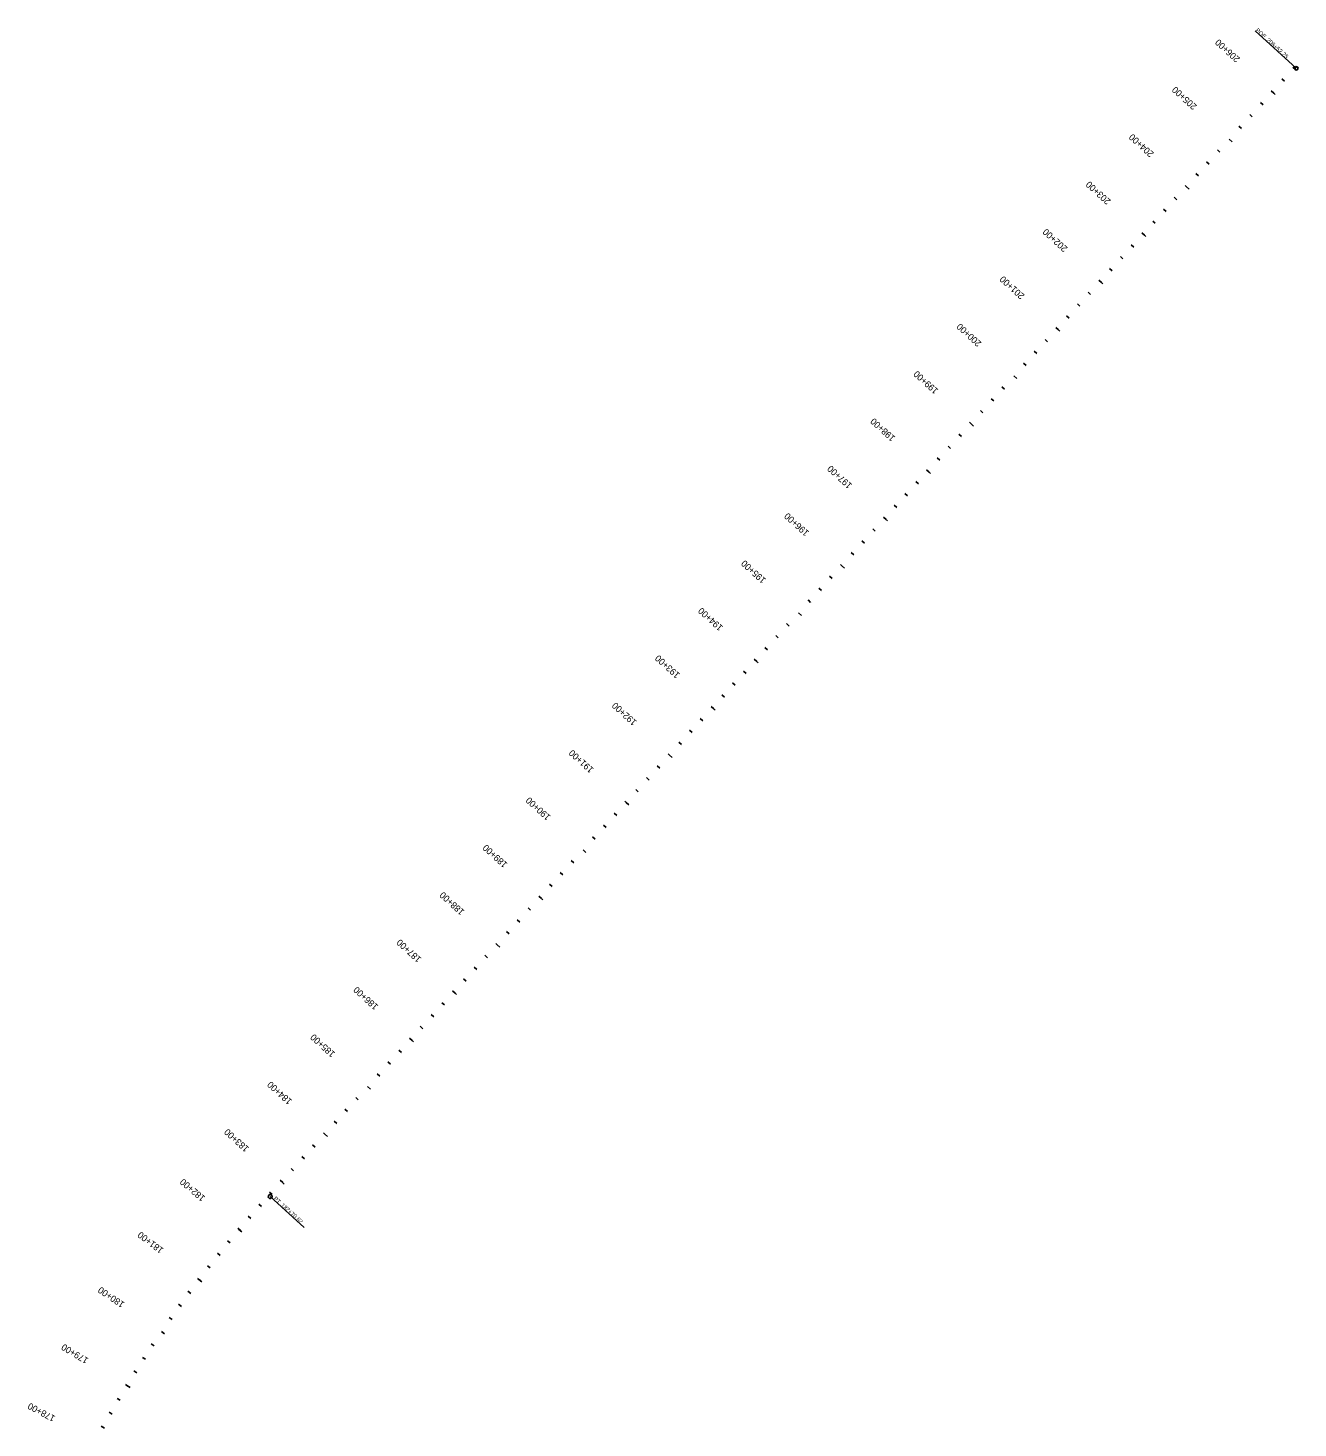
# Model space of a CAD drawing. Extents: x 17535628 to 17537899, y 7333852 to 7342653.
# Drawn here: x 17535915 to 17537899, y 7340467 to 7342653 of the extents above; entities that cross this region are included whole.
import ezdxf

# ---------------------------------------------------------------- set-up
doc = ezdxf.new("R2010")
doc.units = 0
for name, color, linetype in [('TextAlignment', 7, 'Continuous'), ('TextAlignmentLrg', 7, 'Continuous'), ('TextAlignmentSml', 7, 'Continuous')]:
    doc.layers.add(name, color=color, linetype=linetype)

msp = doc.modelspace()

# ---------------------------------------------------------------- linework, layer by layer
at = {"layer": 'TextAlignment'}
for p, q in [((17537895.9, 7342590.2), (17537831.6, 7342648.8)), ((17536293.2, 7340828.6), (17536346.4, 7340780.1))]:
    msp.add_line(p, q, dxfattribs=at)
for centre, radius in [((17537895.9, 7342590.2), 2.67), ((17536293.2, 7340828.6), 3.12)]:
    msp.add_circle(centre, radius, dxfattribs=at)
at = {"layer": 'TextAlignmentLrg'}
for p, q in [((17537860.7, 7342551.6), (17537856.7, 7342555.2)), ((17537791.2, 7342479.7), (17537795.7, 7342475.5)), ((17537726.1, 7342403.6), (17537722.1, 7342407.3)), ((17537658.9, 7342329.7), (17537654.8, 7342333.3)), ((17537591.6, 7342255.7), (17537587.5, 7342259.4)), ((17537524.3, 7342181.7), (17537520.2, 7342185.4)), ((17537454.7, 7342109.8), (17537459.2, 7342105.7)), ((17537389.7, 7342033.8), (17537385.6, 7342037.5)), ((17537322.4, 7341959.8), (17537318.3, 7341963.5)), ((17537255.1, 7341885.9), (17537251, 7341889.5)), ((17537187.8, 7341811.9), (17537183.7, 7341815.6)), ((17537118.2, 7341740), (17537122.8, 7341735.9)), ((17537053.2, 7341663.9), (17537049.2, 7341667.6)), ((17536985.9, 7341590), (17536981.9, 7341593.7)), ((17536918.6, 7341516), (17536914.6, 7341519.7)), ((17536851.3, 7341442), (17536847.3, 7341445.7)), ((17536781.8, 7341370.1), (17536786.3, 7341366)), ((17536716.7, 7341294.1), (17536712.7, 7341297.8)), ((17536649.4, 7341220.1), (17536645.4, 7341223.8)), ((17536582.1, 7341146.2), (17536578.1, 7341149.8)), ((17536514.8, 7341072.2), (17536510.8, 7341075.9)), ((17536445.3, 7341000.3), (17536449.8, 7340996.2)), ((17536380.2, 7340924.3), (17536376.2, 7340927.9)), ((17536312.9, 7340850.3), (17536308.9, 7340854)), ((17536246.6, 7340775.5), (17536242.5, 7340779)), ((17536184.1, 7340697.4), (17536179.8, 7340700.7)), ((17536123.2, 7340618), (17536128.3, 7340614.5)), ((17536071.7, 7340532.1), (17536067, 7340534.9))]:
    msp.add_line(p, q, dxfattribs=at)
at = {"layer": 'TextAlignmentSml'}
for p, q in [((17537894.4, 7342588.6), (17537890.3, 7342592.2)), ((17537877.6, 7342570.1), (17537873.5, 7342573.7)), ((17537858.5, 7342553.6), (17537863, 7342549.5)), ((17537843.9, 7342533.1), (17537839.9, 7342536.7)), ((17537827.1, 7342514.6), (17537823.1, 7342518.3)), ((17537810.3, 7342496.1), (17537806.2, 7342499.8)), ((17537776.6, 7342459.1), (17537772.6, 7342462.8)), ((17537791.2, 7342479.7), (17537795.7, 7342475.5)), ((17537759.8, 7342440.6), (17537755.8, 7342444.3)), ((17537743, 7342422.1), (17537738.9, 7342425.8)), ((17537723.9, 7342405.7), (17537728.4, 7342401.6)), ((17537709.3, 7342385.1), (17537705.3, 7342388.8)), ((17537675.7, 7342348.2), (17537671.6, 7342351.8)), ((17537692.5, 7342366.6), (17537688.5, 7342370.3)), ((17537656.6, 7342331.7), (17537661.1, 7342327.6)), ((17537642, 7342311.2), (17537638, 7342314.8)), ((17537625.2, 7342292.7), (17537621.2, 7342296.4)), ((17537608.4, 7342274.2), (17537604.3, 7342277.9)), ((17537574.7, 7342237.2), (17537570.7, 7342240.9)), ((17537589.3, 7342257.8), (17537593.8, 7342253.6)), ((17537557.9, 7342218.7), (17537553.9, 7342222.4)), ((17537541.1, 7342200.2), (17537537, 7342203.9)), ((17537522, 7342183.8), (17537526.5, 7342179.7)), ((17537507.4, 7342163.2), (17537503.4, 7342166.9)), ((17537490.6, 7342144.7), (17537486.6, 7342148.4)), ((17537454.7, 7342109.8), (17537459.2, 7342105.7)), ((17537473.8, 7342126.2), (17537469.8, 7342129.9)), ((17537440.1, 7342089.3), (17537436.1, 7342092.9)), ((17537423.3, 7342070.8), (17537419.3, 7342074.4)), ((17537406.5, 7342052.3), (17537402.5, 7342056)), ((17537387.4, 7342035.8), (17537391.9, 7342031.7)), ((17537356, 7341996.8), (17537352, 7342000.5)), ((17537372.8, 7342015.3), (17537368.8, 7342019)), ((17537339.2, 7341978.3), (17537335.2, 7341982)), ((17537320.1, 7341961.9), (17537324.6, 7341957.8)), ((17537305.6, 7341941.3), (17537301.5, 7341945)), ((17537288.7, 7341922.8), (17537284.7, 7341926.5)), ((17537271.9, 7341904.3), (17537267.9, 7341908)), ((17537238.3, 7341867.4), (17537234.2, 7341871)), ((17537252.8, 7341887.9), (17537257.3, 7341883.8)), ((17537221.4, 7341848.9), (17537217.4, 7341852.5)), ((17537204.6, 7341830.4), (17537200.6, 7341834)), ((17537185.5, 7341813.9), (17537190.1, 7341809.8)), ((17537171, 7341793.4), (17537166.9, 7341797.1)), ((17537137.3, 7341756.4), (17537133.3, 7341760.1)), ((17537154.1, 7341774.9), (17537150.1, 7341778.6)), ((17537118.2, 7341740), (17537122.8, 7341735.9)), ((17537103.7, 7341719.4), (17537099.6, 7341723.1)), ((17537086.8, 7341700.9), (17537082.8, 7341704.6)), ((17537070, 7341682.4), (17537066, 7341686.1)), ((17537050.9, 7341666), (17537055.5, 7341661.9)), ((17537019.5, 7341627), (17537015.5, 7341630.6)), ((17537036.4, 7341645.5), (17537032.3, 7341649.1)), ((17537002.7, 7341608.5), (17536998.7, 7341612.1)), ((17536983.6, 7341592), (17536988.2, 7341587.9)), ((17536969.1, 7341571.5), (17536965, 7341575.2)), ((17536952.3, 7341553), (17536948.2, 7341556.7)), ((17536935.4, 7341534.5), (17536931.4, 7341538.2)), ((17536901.8, 7341497.5), (17536897.7, 7341501.2)), ((17536916.3, 7341518.1), (17536920.9, 7341513.9)), ((17536885, 7341479), (17536880.9, 7341482.7)), ((17536868.1, 7341460.5), (17536864.1, 7341464.2)), ((17536849, 7341444.1), (17536853.6, 7341440)), ((17536834.5, 7341423.5), (17536830.4, 7341427.2)), ((17536800.8, 7341386.6), (17536796.8, 7341390.2)), ((17536817.7, 7341405.1), (17536813.6, 7341408.7)), ((17536781.8, 7341370.1), (17536786.3, 7341366)), ((17536767.2, 7341349.6), (17536763.2, 7341353.3)), ((17536750.4, 7341331.1), (17536746.3, 7341334.8)), ((17536733.5, 7341312.6), (17536729.5, 7341316.3)), ((17536699.9, 7341275.6), (17536695.9, 7341279.3)), ((17536714.5, 7341296.2), (17536719, 7341292)), ((17536683.1, 7341257.1), (17536679, 7341260.8)), ((17536666.2, 7341238.6), (17536662.2, 7341242.3)), ((17536647.2, 7341222.2), (17536651.7, 7341218.1)), ((17536632.6, 7341201.6), (17536628.6, 7341205.3)), ((17536615.8, 7341183.2), (17536611.7, 7341186.8)), ((17536579.9, 7341148.2), (17536584.4, 7341144.1)), ((17536599, 7341164.7), (17536594.9, 7341168.3)), ((17536565.3, 7341127.7), (17536561.3, 7341131.3)), ((17536548.5, 7341109.2), (17536544.4, 7341112.9)), ((17536531.7, 7341090.7), (17536527.6, 7341094.4)), ((17536512.6, 7341074.3), (17536517.1, 7341070.1)), ((17536481.2, 7341035.2), (17536477.1, 7341038.9)), ((17536498, 7341053.7), (17536494, 7341057.4)), ((17536464.4, 7341016.7), (17536460.3, 7341020.4)), ((17536445.3, 7341000.3), (17536449.8, 7340996.2)), ((17536430.7, 7340979.7), (17536426.7, 7340983.4)), ((17536413.9, 7340961.2), (17536409.9, 7340964.9)), ((17536397.1, 7340942.8), (17536393, 7340946.4)), ((17536363.4, 7340905.8), (17536359.4, 7340909.4)), ((17536378, 7340926.3), (17536382.5, 7340922.2)), ((17536346.6, 7340887.3), (17536342.6, 7340891)), ((17536329.8, 7340868.8), (17536325.7, 7340872.5)), ((17536310.7, 7340852.4), (17536315.2, 7340848.2)), ((17536296.1, 7340831.8), (17536292.1, 7340835.5)), ((17536262.9, 7340794.5), (17536258.8, 7340798)), ((17536279.4, 7340813.2), (17536275.3, 7340816.9)), ((17536244.3, 7340777.4), (17536249, 7340773.5)), ((17536230.6, 7340756.3), (17536226.4, 7340759.7)), ((17536214.9, 7340736.8), (17536210.6, 7340740.3)), ((17536199.4, 7340717.2), (17536195.1, 7340720.6)), ((17536181.7, 7340699.3), (17536186.6, 7340695.6)), ((17536169.1, 7340677.4), (17536164.7, 7340680.7)), ((17536154.4, 7340657.2), (17536150, 7340660.4)), ((17536139.9, 7340636.8), (17536135.5, 7340639.9)), ((17536123.2, 7340618), (17536128.3, 7340614.5)), ((17536111.8, 7340595.5), (17536107.3, 7340598.5)), ((17536098.2, 7340574.5), (17536093.6, 7340577.5)), ((17536084.8, 7340553.4), (17536080.2, 7340556.3)), ((17536069.1, 7340533.7), (17536074.3, 7340530.5)), ((17536058.9, 7340510.7), (17536054.2, 7340513.4)), ((17536046.3, 7340489), (17536041.6, 7340491.7)), ((17536034.1, 7340467.2), (17536029.3, 7340469.9))]:
    msp.add_line(p, q, dxfattribs=at)

# ---------------------------------------------------------------- texts
at = {"layer": 'TextAlignment'}
for s, p in [('POE ', (17537831.6, 7342648.8)), ('206+52.25', (17537848.6, 7342633.4)), ('PT', (17536297.7, 7340824.6)), ('182+70.62', (17536309.2, 7340814.2))]:
    msp.add_text(s, height=6.48, rotation=317.7046, dxfattribs=at).set_placement(p)
at = {"layer": 'TextAlignmentLrg'}
for s, rotation, p in [('205+00', 137.7046, (17537741.4, 7342531.8)), ('200+00', 137.7046, (17537404.9, 7342162)), ('195+00', 137.7046, (17537068.4, 7341792.2)), ('190+00', 137.7046, (17536732, 7341422.3)), ('185+00', 137.7046, (17536395.5, 7341052.5)), ('180+00', 145.7835, (17536066.6, 7340662.6))]:
    msp.add_text(s, height=10.2, rotation=rotation, dxfattribs=at).set_placement(p)
at = {"layer": 'TextAlignmentSml'}
for s, rotation, p in [('206+00', 137.7046, (17537808.7, 7342605.8)), ('205+00', 137.7046, (17537741.4, 7342531.8)), ('204+00', 137.7046, (17537674.1, 7342457.9)), ('203+00', 137.7046, (17537606.8, 7342383.9)), ('202+00', 137.7046, (17537539.5, 7342309.9)), ('201+00', 137.7046, (17537472.2, 7342236)), ('200+00', 137.7046, (17537404.9, 7342162)), ('199+00', 137.7046, (17537337.6, 7342088)), ('198+00', 137.7046, (17537270.3, 7342014.1)), ('197+00', 137.7046, (17537203, 7341940.1)), ('196+00', 137.7046, (17537135.7, 7341866.1)), ('195+00', 137.7046, (17537068.4, 7341792.2)), ('194+00', 137.7046, (17537001.2, 7341718.2)), ('193+00', 137.7046, (17536933.9, 7341644.2)), ('192+00', 137.7046, (17536866.6, 7341570.3)), ('191+00', 137.7046, (17536799.3, 7341496.3)), ('190+00', 137.7046, (17536732, 7341422.3)), ('189+00', 137.7046, (17536664.7, 7341348.3)), ('188+00', 137.7046, (17536597.4, 7341274.4)), ('187+00', 137.7046, (17536530.1, 7341200.4)), ('186+00', 137.7046, (17536462.8, 7341126.4)), ('185+00', 137.7046, (17536395.5, 7341052.5)), ('184+00', 137.7046, (17536328.2, 7340978.5)), ('183+00', 137.7046, (17536260.9, 7340904.5)), ('182+00', 139.8129, (17536192.6, 7340827.8)), ('181+00', 142.7982, (17536127.5, 7340746.8)), ('180+00', 145.7835, (17536066.6, 7340662.6)), ('179+00', 148.7688, (17536010.2, 7340575.4)), ('178+00', 151.7542, (17535958.4, 7340485.3))]:
    msp.add_text(s, height=10.2, rotation=rotation, dxfattribs=at).set_placement(p)

doc.saveas('drawing.dxf')
